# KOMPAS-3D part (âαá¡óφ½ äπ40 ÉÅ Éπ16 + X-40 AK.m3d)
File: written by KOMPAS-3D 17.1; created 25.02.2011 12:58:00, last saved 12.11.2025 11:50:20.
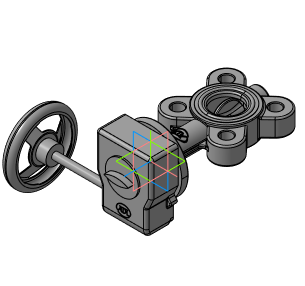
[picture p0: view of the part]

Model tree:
1. Плоскость XY
2. Плоскость ZX
3. Плоскость ZY
4. Ось X
5. Ось Y
6. Ось Z
7. Начало координат
8. Операция без истории:5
